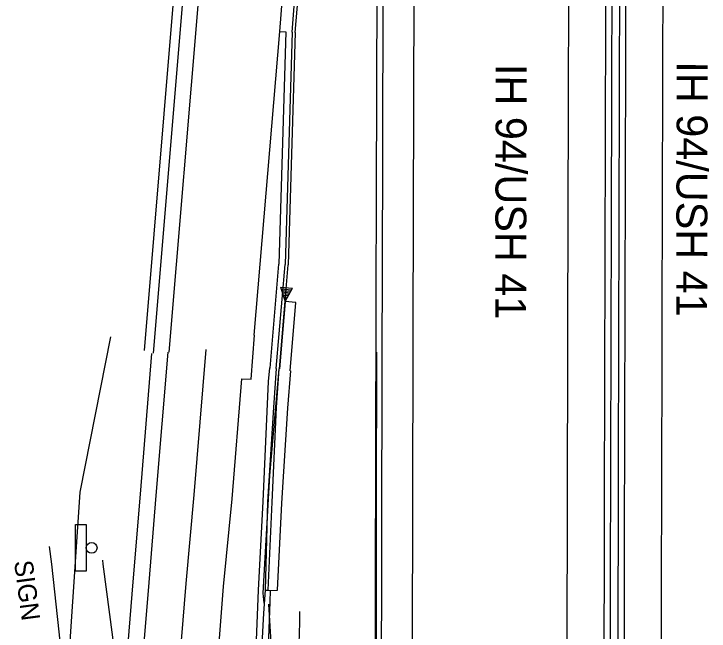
# Model space of a CAD drawing. Extents: x 588843 to 2552415, y 180129 to 269402.
# Drawn here: x 593820.4 to 594045.1, y 186151 to 186350.4 of the extents above; entities that cross this region are included whole.
import ezdxf

# ---------------------------------------------------------------- set-up
doc = ezdxf.new("R2010")
doc.units = 0
for name, color, linetype in [('Default', 7, 'Continuous'), ('E_BMGRD', 7, 'Continuous'), ('E_FEN_P', 7, 'Continuous'), ('E_RDWY', 7, 'Continuous'), ('E_RDWY_AsphConc', 7, 'Continuous'), ('E_RDWY_BarrierConc', 7, 'Continuous'), ('E_RDWY_C_and_G', 7, 'Continuous'), ('E_RDWY_Gravel', 7, 'Continuous'), ('E_RDWY_Text', 7, 'Continuous'), ('E_SGN', 7, 'Continuous'), ('E_SGN_Text', 7, 'Continuous'), ('E_STRUCT_Joint', 7, 'Continuous'), ('E_WAL', 7, 'Continuous'), ('E_WTR_P', 7, 'Continuous'), ('P_BMGRD', 7, 'Continuous'), ('P_RDWY_BarrierConc', 7, 'Continuous'), ('P_RDWY_C_and_G', 7, 'Continuous'), ('P_RDWY_C_and_GBack', 7, 'Continuous'), ('P_RDWY_C_and_GFace', 7, 'Continuous'), ('P_RDWY_PavtEdge', 7, 'Continuous'), ('P_RDWY_ShldAgg', 7, 'Continuous'), ('P_RDWY_ShldPaved', 7, 'Continuous')]:
    doc.layers.add(name, color=color, linetype=linetype)

# ---------------------------------------------------------------- blocks, each defined once
blk = doc.blocks.new('SGN_1')
at = {"layer": 'Default'}
blk.add_lwpolyline([(-3.5, -15), (-10.5, -15), (-10.5, 15), (-3.5, 15)], close=True, dxfattribs=at)
blk.add_circle((0, 0), 3.5, dxfattribs=at)
blk = doc.blocks.new('SIGN_3')
at = {"layer": 'E_SGN'}
blk.add_text('SIGN', height=39.37, dxfattribs=at).set_placement((-56.1, -19.7))

msp = doc.modelspace()

# ---------------------------------------------------------------- linework, layer by layer
at = {"layer": 'E_BMGRD'}
msp.add_lwpolyline([(593901.26, 186159.99), (593900.95, 186163.21), (593903.08, 186201.24), (593906.08, 186235.75)], dxfattribs=at)
at = {"layer": 'E_FEN_P'}
for points in [[(593912.77, 186153.81), (593912.86, 186157.34)], [(593912.51, 186143.46), (593912.77, 186153.81)]]:
    msp.add_lwpolyline(points, dxfattribs=at)
at = {"layer": 'E_RDWY'}
for points in [[(593836.13, 185745.12), (593841.89, 185765.08), (593845.72, 185781.36), (593847.4, 185793.04), (593848.32, 185808.55), (593848.31, 185830.42), (593847.95, 185856.84), (593847.65, 185880.3), (593847.24, 185907.21), (593847.03, 185929.27), (593846.61, 185949.53), (593846.25, 185969.24), (593845.46, 185992.34), (593844.66, 186014), (593843.59, 186032.87), (593842.94, 186049.89), (593841.92, 186067.35), (593840.48, 186088.51), (593838.83, 186111.83), (593836.93, 186131.65), (593835, 186150.73), (593832.59, 186172.59), (593831.82, 186178.37)], [(593873.35, 185748.14), (593873.39, 185767.91), (593873.13, 185789.39), (593873.03, 185813.38), (593872.75, 185836.74), (593872.7, 185858.91), (593872.47, 185877.2), (593872.47, 185897.55), (593872.27, 185918.64), (593871.98, 185943.2), (593871.78, 185963.03), (593871.7, 185982.99), (593871.47, 186006.16), (593871.15, 186023.46), (593870.22, 186035.53), (593868.69, 186047.14), (593865.76, 186062.4), (593862.09, 186082.41), (593858.59, 186101.83), (593854.78, 186126.1), (593852.31, 186149.03), (593849.25, 186172.64), (593849.08, 186173.88)]]:
    msp.add_lwpolyline(points, dxfattribs=at)
at = {"layer": 'E_RDWY_AsphConc'}
for points in [[(593855.43, 186124.4), (593858.92, 186166.88), (593861.32, 186195.27), (593864.95, 186240.71)], [(593901.71, 186164.18), (593902.55, 186164.19), (593903.28, 186164.11), (593905.58, 186164.2), (593907.03, 186192.34), (593908.92, 186222.97), (593909.87, 186235.06)]]:
    msp.add_lwpolyline(points, dxfattribs=at)
at = {"layer": 'E_RDWY_BarrierConc'}
msp.add_lwpolyline([(593937.57, 186241.13), (593937.46, 186191.77), (593937.44, 186142.33), (593937.33, 186091.78), (593937.2, 186041.14), (593937.14, 185989.12), (593937.29, 185932.98), (593937.11, 185882.1), (593937.27, 185829.01), (593937.27, 185779.4), (593936.91, 185723.47), (593936.92, 185706.41)], dxfattribs=at)
at = {"layer": 'E_RDWY_C_and_G'}
for points in [[(593899.24, 186120.75), (593897.73, 186121.04), (593899.43, 186164.19), (593900.97, 186192.91), (593902.73, 186231.68), (593903.07, 186235.99)], [(593901.71, 186164.18), (593902.42, 186192.8), (593904.38, 186223.26), (593905.27, 186235.78)], [(593902.55, 186164.19), (593903.86, 186192.61), (593905.29, 186223.19), (593906.08, 186235.75)]]:
    msp.add_lwpolyline(points, dxfattribs=at)
at = {"layer": 'E_RDWY_Gravel'}
msp.add_lwpolyline([(593851.63, 186246.08), (593841.69, 186195.87), (593836.95, 186125.17), (593837.99, 186083.85), (593832.3, 186038.12), (593834.91, 185985.81), (593830.41, 185937.11), (593828.76, 185889.27)], dxfattribs=at)
at = {"layer": 'E_STRUCT_Joint'}
for points in [[(593897.05, 186232.35), (593898.19, 186246.61)], [(593860.55, 186123.99), (593864.07, 186166.75), (593866.39, 186194.82), (593870.23, 186241.08)], [(593872.53, 186122.93), (593876.1, 186166.41), (593878.67, 186195.01), (593882.51, 186242.01)], [(593884.79, 186121.86), (593888.16, 186165.36), (593890.88, 186193.71), (593894.04, 186232.53), (593897.05, 186232.35)]]:
    msp.add_lwpolyline(points, dxfattribs=at)
at = {"layer": 'E_WAL'}
msp.add_lwpolyline([(593901.39, 186120.33), (593899.24, 186120.75), (593901.15, 186156.8), (593901.71, 186164.18), (593903.27, 186164.06), (593903.11, 186160.4), (593901.92, 186128.52), (593901.86, 186121.92)], dxfattribs=at)
at = {"layer": 'E_WTR_P'}
msp.add_lwpolyline([(593902.68, 186159.65), (593903.33, 186149.06), (593903.17, 186132.89), (593903.08, 186130.28)], dxfattribs=at)
at = {"layer": 'P_BMGRD'}
for p, q in [((593906.51, 186262.1), (593908.09, 186257.45)), ((593906.51, 186262.1), (593910.45, 186261.76)), ((593906.69, 186261.58), (593910.18, 186261.28)), ((593908.09, 186257.45), (593910.45, 186261.76)), ((593906.86, 186261.07), (593909.93, 186260.8)), ((593907.04, 186260.55), (593909.66, 186260.32)), ((593907.21, 186260.03), (593909.4, 186259.84)), ((593907.39, 186259.52), (593909.14, 186259.37)), ((593907.57, 186259), (593908.88, 186258.88)), ((593908.09, 186257.45), (593906.21, 186235.71)), ((593908.09, 186257.44), (593907.64, 186252.19)), ((593907.74, 186258.48), (593908.61, 186258.4)), ((593907.92, 186257.96), (593908.35, 186257.93))]:
    msp.add_line(p, q, dxfattribs=at)
at = {"layer": 'P_RDWY_BarrierConc'}
for radius, start, end in [(137507.12, 179.769059, 180.1191305), (137505.12, 179.769059, 180.1191305), (137502.62, 179.769059, 180.1203068), (137500.62, 179.769059, 180.1203068), (137581.12, 179.7862412, 180.0810951), (137579.12, 179.7862412, 180.081095)]:
    msp.add_arc((731518.05, 185900.98), radius, start, end, dxfattribs=at)
at = {"layer": 'P_RDWY_C_and_G'}
for p, q in [((593906.31, 186344.74), (593929.72, 186624.21)), ((593908.3, 186344.58), (593906.03, 186269.5)), ((593906.31, 186344.74), (593908.3, 186344.58)), ((593903.22, 186235.97), (593906.03, 186269.5))]:
    msp.add_line(p, q, dxfattribs=at)
at = {"layer": 'P_RDWY_C_and_GBack'}
for p, q in [((593911.3, 186344.41), (593934.74, 186624.19)), ((593911.3, 186344.41), (593909.03, 186269.33)), ((593906.21, 186235.71), (593909.03, 186269.33))]:
    msp.add_line(p, q, dxfattribs=at)
at = {"layer": 'P_RDWY_C_and_GFace'}
for p, q in [((593910.3, 186344.46), (593933.73, 186624.19)), ((593910.3, 186344.46), (593908.03, 186269.39)), ((593905.21, 186235.78), (593908.03, 186269.39))]:
    msp.add_line(p, q, dxfattribs=at)
at = {"layer": 'P_RDWY_PavtEdge'}
for p, q in [((593870.53, 186241.1), (593888.49, 186455.5)), ((593898.09, 186246.57), (593906.31, 186344.74)), ((593911.52, 186257.15), (593908.03, 186257.45)), ((593909.67, 186235.09), (593911.52, 186257.15))]:
    msp.add_line(p, q, dxfattribs=at)
for radius, end in [(137569.12, 180.0933637), (137519.12, 180.0933589), (137488.62, 180.1079179)]:
    msp.add_arc((731518.05, 185900.98), radius, 179.769059, end, dxfattribs=at)
at = {"layer": 'P_RDWY_ShldAgg'}
msp.add_line((593862.55, 186241.68), (593880.54, 186456.43), dxfattribs=at)
at = {"layer": 'P_RDWY_ShldPaved'}
msp.add_line((593865.49, 186240.75), (593883.52, 186456.08), dxfattribs=at)

# ---------------------------------------------------------------- block references
at = {"layer": 'E_SGN', "xscale": 0.5, "yscale": 0.5}
msp.add_blockref('SGN_1', (593845.48, 186177.89), dxfattribs=at)
at = {"layer": 'E_SGN_Text', "xscale": 0.1524003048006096, "yscale": 0.15240030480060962, "rotation": -82.47523273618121}
msp.add_blockref('SIGN_3', (593824.48, 186165.4), dxfattribs=at)

# ---------------------------------------------------------------- texts
at = {"layer": 'E_RDWY_Text'}
for p in [(594034.69, 186335.06), (593976.16, 186334.22)]:
    msp.add_text('IH 94/USH 41', height=10, rotation=269.8747, dxfattribs=at).set_placement(p)

doc.saveas('drawing.dxf')
